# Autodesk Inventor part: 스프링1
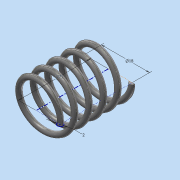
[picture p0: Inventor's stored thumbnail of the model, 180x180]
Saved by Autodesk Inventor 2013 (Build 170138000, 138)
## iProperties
Created: 2016-10
Part Number: 스프링1
Material: 강철, 탄소
Document SubType Name: Modeling
Designer: user
Mass: 6.88075 g
Surface Area: 17.7314 cm^2
Volume: 0.874302 cm^3
Density: 7.87 g/cm^3
Author: user
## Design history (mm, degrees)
sketch "스케치1"
  geometry: L1 (0, 0)-(9, 0); L2 (9, 0)-(9, 27); L3 (9, 27)-(0, 27); L4 (0, 27)-(0, 0); C1 r 1 at (9, 0)
  constraints: 8 end point, 2 parallel, 1 centre point, 1 coincident, 1 horizontal, 1 perpendicular
  dimensions: "d0" = 27 distance of L3.end L1.start (derived); "d1" = 18 diameter of L2 L4; "d2" = 2 diameter of C1
feature "코일1" pitch "d3" = 10; turns "d5" = 5; dims "d4" = 27 (= d0), "d6" = 0, angle "d7" = 90 deg, angle "d8" = 90 deg, "d9" = 0, "d10" = 0
sketch "스케치2"
  geometry: L1 (-8, 0)-(-10, 0) reference; 1 further point
  constraints: 1 horizontal alignment
extrude "돌출1" cut sketch "스케치2" distance "d11" = 10; taper "d12" = 0 deg
node "작업 평면1"
sketch "스케치3"
  geometry: L1 (-1, 0)-(1, 0) reference; 1 further point
  constraints: 1 horizontal alignment
extrude "돌출2" cut sketch "스케치3" distance "d14" = 10; taper "d15" = 0 deg
node "솔리드1"
node "절단 모서리 투영1"
node "절단 모서리 투영2"
other parameters: "d13" = 0
